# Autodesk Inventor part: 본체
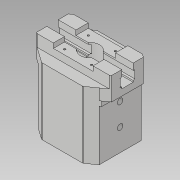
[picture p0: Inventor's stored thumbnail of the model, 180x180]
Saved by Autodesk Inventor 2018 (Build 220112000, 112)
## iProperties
Created: 2023-05
Part Number: 본체
Material: 일반
Document SubType Name: Modeling
Designer: home
Density: 1 g/cm^3
Appearance: 기본값
Author: home
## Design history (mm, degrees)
sketch "스케치1"
  geometry: L1 (-40, -35)-(40, -35); L2 (40, -35)-(40, 35); L3 (40, 35)-(-40, 35); L4 (-40, 35)-(-40, -35); L5 (-40, -35)-(40, 35); L6 (40, -35)-(-40, 35); 1 further point
  constraints: 12 end point, 2 midpoint, 2 parallel, 1 horizontal, 1 perpendicular
  dimensions: "d0" = 80 distance of L3.end L2.end; "d1" = 70 distance of L2.end L1.end
extrude "돌출1" new body sketch "스케치1" distance "d2" = 70; taper "d3" = 0 deg
sketch "스케치2"
  geometry: L1 (-40, -35)-(-40, 35) reference; L2 (-40, 35)-(40, 35) reference; L3 (40, 35)-(40, -35) reference; L4 (40, -35)-(-40, -35) reference; L5 (-40, -35)-(40, -35) reference; L6 (-26, -35)-(-47.241, -20); L7 (-47.241, 20)-(-26, 35); L8 (-47.241, 20)-(-47.241, -20); L9 (-26, 35)-(26, 35); L10 (-26, -35)-(26, -35); L11 (47.241, 20)-(26, 35); L12 (47.241, 20)-(47.241, -20); L13 (26, -35)-(47.241, -20); L14 (-26, -35)-(26, -35); 1 further point
  constraints: 18 end point, 2 parallel, 1 collinear
extrude "돌출2" join sketch "스케치2" distance "d10" = 29; taper "d11" = 0 deg
sketch "스케치3"
  geometry: L1 (0.814, 99)-(0.814, 78); L2 (-21.186, 99)-(-21.186, 84); L3 (22.814, 99)-(22.814, 84); L4 (-35, 70)-(-35, 99) reference; L5 (-35, 84)-(-35, 99); L6 (35, 99)-(22.814, 99); L7 (35, 99)-(20, 99) reference; L8 (35, 99)-(35, 84); L9 (35, 70)-(35, 99) reference; L10 (-35, 84)-(-21.186, 84); L11 (-20, 99)-(-35, 99) reference; L12 (22.814, 84)-(35, 84); 2 further points
  constraints: 16 end point, 2 collinear, 2 parallel, 2 perpendicular, 1 point on line, 1 vertical
  dimensions: "d12" = 21 distance of L1.start L1.end; "d13" = 22 distance between parallel lines of L1 L2; "d14" = 22 distance between parallel lines of L1 L3; "d17" = 15 distance between parallel lines of L11 L10
extrude "돌출3" cut sketch "스케치3" extent not by distance; stored distance "d15" = 29; taper "d16" = 0 deg
sketch "스케치4"
  geometry: L1 (-21.186, 84)-(-21.186, 99) reference; L2 (-21.186, 99)-(22.814, 99) reference; L3 (22.814, 99)-(22.814, 84) reference; L4 (22.814, 84)-(35, 84) reference; L5 (35, 84)-(35, 0) reference; L6 (35, 0)-(-35, 0) reference; L7 (-35, 0)-(-35, 84) reference; L8 (-35, 84)-(-21.186, 84) reference; L9 (20, 99)-(-20, 99) reference; L10 (-7.2, 78)-(7.2, 78); L11 (-9, 99)-(9, 99); L12 (9.368, 80.581)-(9.368, 90.419); L13 (7.2, 91)-(9.368, 90.419); L14 (7.2, 80)-(9.368, 80.581); L15 (9.368, 80)-(10.883, 80); L16 (-7.2, 91)-(-9.368, 90.419); L17 (-9.368, 80.581)-(-9.368, 90.419); L18 (-7.2, 80)-(-9.368, 80.581); L19 (-7.2, 99)-(-7.2, 91); L20 (-7.2, 80)-(-7.2, 78); L21 (7.2, 99)-(7.2, 91); L22 (7.2, 80)-(7.2, 78); L23 (-7.2, 99)-(7.2, 99); 1 further point
  constraints: 28 end point, 3 horizontal, 1 point on line
  dimensions: "d30" = 15 deg angle of L15 L14
extrude "돌출4" cut sketch "스케치4" extent not by distance; stored distance "d31" = 29; taper "d32" = 0 deg
sketch "스케치5"
  geometry: C1 r 30 at (0, 0); 1 further point
  constraints: 1 centre point, 1 coincident
  dimensions: "d33" = 60 diameter of C1
extrude "돌출5" cut sketch "스케치5" distance "d34" = 5.8; taper "d35" = 0 deg
hole "구멍1" diameter "d38" = 60; stored, may be unused: countersink angle "d42" = 90 deg, drill point angle "d44" = 0 deg; dims "d39" = 6, "d40" = 63, "d41" = 2.2, "d43" = 8.8, "d45" = 10, "d46" = 10
hole "구멍2" diameter "d49" = 50; stored, may be unused: countersink angle "d53" = 110 deg, drill point angle "d55" = 0 deg; dims "d50" = 6, "d51" = 52, "d52" = 2.2, "d54" = 45, "d103" = 10, "d104" = 10
chamfer "모따기1" distance "d58" = 1; stored, may be unused: second distance "d59" = 2, angle "d60" = 45 deg
sketch "스케치6"
  geometry: L1 (40, -35)-(-40, -35) reference; L2 (-40, -35)-(-40, 35) reference; L3 (-40, 35)-(40, 35) reference; L4 (40, 35)-(40, -35) reference; L5 (-43.256, 22.814)-(-47.241, 20) reference; L6 (-47.241, 20)-(-24.231, 36.249); L7 (-47.241, 20)-(-47.241, 36.249); L8 (-47.241, 36.249)-(-24.231, 36.249); L9 (47.305, 20)-(24.131, 36.249); L10 (24.131, 36.249)-(47.305, 36.249); L11 (40, 35)-(-40, 35) reference; L12 (47.305, 20)-(47.305, 36.249); C1 r 31 at (0, 0) reference; 1 further point
  constraints: 12 end point, 2 perpendicular, 1 collinear, 1 parallel, 1 vertical
extrude "돌출6" cut sketch "스케치6" extent not by distance; stored distance "d61" = 5.8; taper "d62" = 0 deg
fillet "모깎기1" dims "d63" = 3
fillet "모깎기2" dims "d64" = 3
sketch "스케치7"
  geometry: L1 (5.563, -29)-(0, -29) reference; L2 (0, -29)-(0, -15) reference; L3 (0, -15)-(91.125, -15) reference; L4 (91.125, 0)-(91.125, -15) reference; L5 (0, 0)-(91.125, 0) reference; L6 (0, -15)-(0, 0) reference; L7 (5.563, -99)-(5.563, -29) reference; L8 (22.931, -99)-(5.563, -99) reference; L9 (24.322, -93.2)-(24.322, -98) reference; L10 (22.251, -93.2)-(24.322, -93.2) reference; L11 (22.251, -91)-(22.251, -93.2) reference; L12 (24.322, -91)-(22.251, -91) reference; L13 (24.322, -84.4)-(24.322, -91) reference; L14 (32.29, -39.4)-(32.29, -83.7) reference; L15 (58.835, -39.4)-(32.29, -39.4) reference; L16 (58.835, -83.7)-(58.835, -39.4) reference; L17 (66.803, -91)-(66.803, -84.4) reference; L18 (68.874, -91)-(66.803, -91) reference; L19 (68.874, -93.2)-(68.874, -91) reference; L20 (66.803, -93.2)-(68.874, -93.2) reference; L21 (66.803, -98)-(66.803, -93.2) reference; L22 (85.563, -99)-(68.194, -99) reference; L23 (85.563, -29)-(85.563, -99) reference; L24 (91.125, -29)-(85.563, -29) reference; L25 (91.125, -15)-(91.125, -29) reference; L26 (92.804, 0)-(-1.679, 0) reference; L27 (70.563, 0)-(70.563, -6); L28 (20.563, 0)-(20.563, -6); L29 (20.563, -6)-(70.563, -6); L30 (20.563, 0)-(70.563, 0); L31 (30.49, -84.4)-(24.322, -84.4) reference; L32 (66.803, -84.4)-(60.635, -84.4) reference; 1 further point
  constraints: 8 end point, 1 collinear, 1 horizontal, 4 other
extrude "돌출7" cut sketch "스케치7" extent not by distance; stored distance "d70" = 5.8; taper "d71" = 0 deg
sketch "스케치8"
  geometry: L1 (47.241, 70)-(40, 70) reference; L2 (40, 70)-(40, 0) reference; L3 (40, 0)-(31, 0) reference; L4 (31, 0)-(30, 1) reference; L5 (30, 1)-(30, 5.8) reference; L6 (30, 5.8)-(31.5, 5.8) reference; L7 (31.5, 5.8)-(31.5, 8) reference; L8 (31.5, 8)-(30, 8) reference; L9 (30, 8)-(30, 14.6) reference; L10 (26, 14.6)-(25, 15.3) reference; L11 (25, 15.3)-(25, 59.6) reference; L12 (25, 59.6)-(-25, 59.6) reference; L13 (-25, 59.6)-(-25, 15.3) reference; L14 (-25, 15.3)-(-26, 14.6) reference; L15 (-30, 14.6)-(-30, 8) reference; L16 (-30, 8)-(-31.5, 8) reference; L17 (-31.5, 8)-(-31.5, 5.8) reference; L18 (-31.5, 5.8)-(-30, 5.8) reference; L19 (-30, 5.8)-(-30, 1) reference; L20 (-30, 1)-(-31, 0) reference; L21 (-31, 0)-(-40, 0) reference; L22 (-40, 0)-(-40, 70) reference; L23 (-40, 70)-(-47.241, 70) reference; L24 (-47.241, 70)-(-47.241, 78) reference; L25 (-47.241, 78)-(47.241, 78) reference; L26 (47.241, 78)-(47.241, 70) reference; L27 (-40, 0)-(-38, 0); L28 (-26.688, 0)-(-40, 0) reference; L29 (-38, 0)-(-38, 64); L30 (-40, 0)-(-40, 64); L31 (-38, 64)-(-40, 64); L32 (30, 14.6)-(26, 14.6) reference; L33 (-26, 14.6)-(-30, 14.6) reference; 1 further point
  constraints: 8 end point, 2 perpendicular, 1 collinear, 1 point on line
  dimensions: "d72" = 2 distance of L21.end L27.end; "d73" = 64 distance from line of L27.end L31
extrude "돌출8" cut sketch "스케치8" extent not by distance; stored distance "d74" = 5.8; taper "d75" = 0 deg
sketch "스케치9"
  geometry: L1 (-78, 19.324)-(-78, 33.724) reference; L2 (-78, 33.724)-(-80, 33.724) reference; L3 (-80, 33.724)-(-80.581, 35.892) reference; L4 (-80.581, 35.892)-(-90.419, 35.892) reference; L5 (-90.419, 35.892)-(-91, 33.724) reference; L6 (-91, 33.724)-(-99, 33.724) reference; L7 (-99, 33.724)-(-99, 49.339) reference; L8 (-99, 49.339)-(-84, 49.339) reference; L9 (-84, 49.339)-(-84, 53.049) reference; L10 (-84, 53.049)-(-64, 53.049) reference; L11 (-64, 53.049)-(-64, 0) reference; L12 (0, 0)-(-64, 0) reference; L13 (0, 53.049)-(0, 0) reference; L14 (-64, 53.049)-(0, 53.049) reference; L15 (-80, 19.324)-(-78, 19.324) reference; L16 (-80.581, 17.156)-(-80, 19.324) reference; L17 (-90.419, 17.156)-(-80.581, 17.156) reference; L18 (-91, 19.324)-(-90.419, 17.156) reference; L19 (-99, 19.324)-(-91, 19.324) reference; L20 (-99, 5.339)-(-99, 19.324) reference; L21 (-84, 5.339)-(-99, 5.339) reference; L22 (-84, 0)-(-84, 5.339) reference; L23 (-64, 0)-(-84, 0) reference; L24 (0, 26.524)-(-28, 26.524); L25 (-28, 26.524)-(-56, 26.524)
  constraints: 4 end point, 2 horizontal
  dimensions: "d76" = 28 distance of L24.start L24.end; "d84" = 28 distance of L24.end L25.end
hole "구멍4" sketch "스케치9" at (-56, 26.524), (-28, 26.524) diameter "d85" = 7.134; stored, may be unused: countersink angle "d89" = 110 deg, drill point angle "d91" = 118 deg; dims "d86" = 7, "d87" = 60, "d88" = 2.2, "d90" = 11
sketch "스케치10"
  geometry: L1 (0, -14.4)-(0, -28.386) reference; L2 (50, -28.386)-(0, -28.386) reference; L3 (70.563, -28.386)-(50, -28.386) reference; L4 (72.241, -27.2)-(70.563, -28.386) reference; L5 (72.241, -14.4)-(72.241, -27.2) reference; L6 (50, -14.4)-(72.241, -14.4) reference; L7 (50, -28.386)-(50, -14.4) reference; L8 (0, -14.4)-(50, -14.4) reference; L9 (-22.241, -14.4)-(0, -14.4) reference; L10 (-22.241, -27.2)-(-22.241, -14.4) reference; L11 (-20.563, -28.386)-(-22.241, -27.2) reference; L12 (0, -28.386)-(-20.563, -28.386) reference; L13 (50, 0)-(50, 15.614) reference; L14 (0, 15.614)-(50, 15.614) reference; L15 (-18.256, 15.614)-(0, 15.614) reference; L16 (-22.241, 12.8)-(-18.256, 15.614) reference; L17 (-22.241, 0)-(-22.241, 12.8) reference; L18 (0, 0)-(-22.241, 0) reference; L19 (0, 15.614)-(0, 0) reference; L20 (50, 0)-(0, 0) reference; L21 (72.241, 0)-(50, 0) reference; L22 (72.241, 12.8)-(72.241, 0) reference; L23 (68.256, 15.614)-(72.241, 12.8) reference; L24 (50, 15.614)-(68.256, 15.614) reference; C1 r 12 at (25, -7.2); 1 further point
  constraints: 1 centre point, 1 coincident
  dimensions: "d92" = 12 radius of C1
extrude "돌출9" cut sketch "스케치10" extent not by distance; stored distance "d93" = 5.8; taper "d94" = 0 deg
sketch "스케치12"
  geometry: L1 (72.207, -27.8)-(22.194, -27.8) reference; L2 (20.463, -27.251)-(0, -12.8) reference; L3 (0, -12.8)-(0, 0) reference; L4 (0, 0)-(37.641, 0) reference; L5 (94.483, 14.4)-(56.841, 14.4) reference; L6 (94.483, 27.2)-(94.483, 14.4) reference; L7 (85.561, 33.5)-(94.483, 27.2) reference; L8 (73.929, 41.656)-(85.561, 33.5) reference; L9 (22.194, 42.2)-(72.207, 42.2) reference; L10 (0, 27.2)-(20.463, 41.651) reference; L11 (0, 14.4)-(0, 27.2) reference; L12 (0, 0)-(0, 14.4) reference; L13 (85.561, -19.1)-(73.929, -27.256) reference; L14 (94.483, -12.8)-(85.561, -19.1) reference; L15 (94.483, 0)-(94.483, -12.8) reference; L16 (56.841, 0)-(94.483, 0) reference; L17 (94.483, 14.4)-(94.483, 0) reference; L18 (37.641, 14.4)-(0, 14.4) reference; L19 (18.241, 13.2)-(76.241, 13.2); L20 (18.241, 1.2)-(76.241, 1.2); A1 r 12 centre (47.241, 7.2) between (37.641, 14.4) and (37.641, 0) reference; A2 r 3 centre (72.207, -24.8) between (72.207, -27.8) and (73.929, -27.256) reference; A3 r 3 centre (22.194, -24.8) between (20.463, -27.251) and (22.194, -27.8) reference; A4 r 12 centre (47.241, 7.2) between (37.641, 0) and (56.841, 0) reference; A5 r 12 centre (47.241, 7.2) between (56.841, 0) and (56.841, 14.4) reference; A6 r 3 centre (72.207, 39.2) between (73.929, 41.656) and (72.207, 42.2) reference; A7 r 3 centre (22.194, 39.2) between (22.194, 42.2) and (20.463, 41.651) reference; A8 r 12 centre (47.241, 7.2) between (37.641, 14.4) and (37.641, 0) reference; A9 r 12 centre (47.241, 7.2) between (56.841, 14.4) and (37.641, 14.4) reference; A10 r 6 centre (18.241, 7.2) between (18.241, 13.2) and (18.241, 1.2); A11 r 6 centre (76.241, 7.2) between (76.241, 1.2) and (76.241, 13.2); 1 further point
  constraints: 4 end point, 4 point on circle, 2 centre point, 1 coincident, 1 tangent
extrude "돌출10" cut sketch "스케치12" distance "d101" = 9; taper "d102" = 0 deg
sketch "스케치13"
  geometry: 1 further point
fillet "모깎기3" dims "d105" = 2
sketch "스케치14"
  geometry: L1 (72.241, -15.614)-(50, -15.614) reference; L2 (50, -15.614)-(34.6, -15.614) reference; L3 (15.4, -15.614)-(0, -15.614) reference; L4 (0, -15.614)-(-22.241, -15.614) reference; L5 (-22.241, -15.614)-(-22.241, -2.814) reference; L6 (-22.241, -2.814)-(-18.256, 0) reference; L7 (-18.256, 0)-(0, 0) reference; L8 (0, 0)-(0, -15.614) reference; L9 (72.241, -2.814)-(72.241, -15.614) reference; L10 (68.256, 0)-(72.241, -2.814) reference; L11 (50, 0)-(68.256, 0) reference; L12 (50, -15.614)-(50, 0) reference; L13 (0, 0)-(50, 0) reference; L14 (0, -30.014)-(0, -44) reference; L15 (50, -44)-(0, -44) reference; L16 (70.563, -44)-(50, -44) reference; L17 (72.241, -42.814)-(70.563, -44) reference; L18 (72.241, -30.014)-(72.241, -42.814) reference; L19 (50, -30.014)-(72.241, -30.014) reference; L20 (34.6, -30.014)-(50, -30.014) reference; L21 (0, -30.014)-(15.4, -30.014) reference; L22 (-22.241, -30.014)-(0, -30.014) reference; L23 (-22.241, -42.814)-(-22.241, -30.014) reference; L24 (-20.563, -44)-(-22.241, -42.814) reference; L25 (0, -44)-(-20.563, -44) reference; L26 (50, -44)-(50, -30.014) reference; L27 (8, -37.814)-(42, -37.814); L28 (42, -37.814)-(42, -7.814); L29 (42, -7.814)-(8, -7.814); L30 (8, -7.814)-(8, -37.814); L31 (8, -37.814)-(42, -7.814); L32 (42, -37.814)-(8, -7.814); A1 r 12 centre (25, -22.814) between (34.6, -15.614) and (15.4, -15.614) reference; A2 r 12 centre (25, -22.814) between (15.4, -30.014) and (34.6, -30.014) reference
  constraints: 12 end point, 2 midpoint, 2 parallel, 1 horizontal, 1 perpendicular
  dimensions: "d106" = 34 distance of L29.end L28.end; "d107" = 30 distance of L28.end L27.end
hole "구멍5" sketch "스케치14" at (8, -7.814), (42, -7.814), (8, -37.814), (42, -37.814) diameter "d108" = 2.459; stored, may be unused: countersink angle "d112" = 110 deg, drill point angle "d114" = 118 deg; dims "d109" = 6, "d110" = 60, "d111" = 2.2, "d113" = 8
sketch "스케치15"
  geometry: L1 (-26, 25)-(26, 25); L2 (26, 25)-(26, -25); L3 (26, -25)-(-26, -25); L4 (-26, -25)-(-26, 25); L5 (-26, 25)-(26, -25); L6 (26, 25)-(-26, -25); C1 r 31 at (0, 0) reference
  constraints: 12 end point, 2 midpoint, 2 parallel, 1 horizontal, 1 perpendicular
  dimensions: "d115" = 52 distance of L2.end L3.end; "d116" = 50 distance of L1.end L2.end
hole "구멍6" sketch "스케치15" at (-26, 25), (26, 25), (26, -25), (-26, -25) diameter "d117" = 4.917; stored, may be unused: countersink angle "d121" = 110 deg, drill point angle "d123" = 118 deg; dims "d118" = 12, "d119" = 60, "d120" = 2.2, "d122" = 14
node "솔리드1"
mirror "미러1"
node "절단 모서리 투영1"
node "절단 모서리 투영2"
node "절단 모서리 투영3"
node "절단 모서리 투영4"
node "절단 모서리 투영5"
node "절단 모서리 투영6"
node "절단 모서리 투영7"
node "절단 모서리 투영9"
node "절단 모서리 투영10"
other parameters: "d24" = 7.2, "d25" = 7.2
